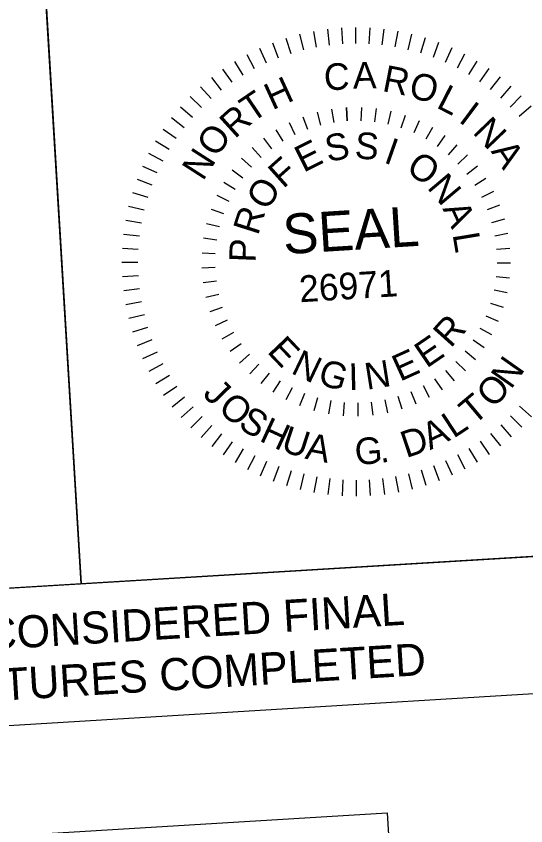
# Model space of a CAD drawing. Extents: x 2110128 to 2112690, y 669500 to 671339.
# Drawn here: x 2112336.1 to 2112423.5, y 670613.2 to 670751.9 of the extents above; entities that cross this region are included whole.
import ezdxf

# ---------------------------------------------------------------- set-up
doc = ezdxf.new("R2010")
doc.units = 0
for name, color, linetype in [('Default', 7, 'Continuous'), ('Exist Roads Curbs Text', 7, 'Continuous'), ('Exist Utilities Power Transformer Cogo Comment', 7, 'Continuous'), ('Exist Utilities TV Test Hole SUE LOS A Text', 7, 'Continuous'), ('Exist Utilities Water Fire Hydrant CELL', 7, 'Continuous')]:
    doc.layers.add(name, color=color, linetype=linetype)

msp = doc.modelspace()

# ---------------------------------------------------------------- linework, layer by layer
at = {"layer": 'Default'}
for p, q in [((2112384.7, 670748.79), (2112385.36, 670746.13)), ((2112387.07, 670749.3), (2112387.57, 670746.61)), ((2112389.47, 670749.67), (2112389.8, 670746.95)), ((2112391.88, 670749.89), (2112392.06, 670747.16)), ((2112394.31, 670749.97), (2112394.32, 670747.24)), ((2112396.73, 670749.9), (2112396.58, 670747.17)), ((2112399.15, 670749.69), (2112398.83, 670746.97)), ((2112401.54, 670749.33), (2112401.06, 670746.64)), ((2112403.92, 670748.83), (2112403.27, 670746.16)), ((2112380.08, 670747.34), (2112381.05, 670744.78)), ((2112382.37, 670748.13), (2112383.19, 670745.52)), ((2112406.26, 670748.18), (2112405.44, 670745.56)), ((2112408.55, 670747.39), (2112407.59, 670744.83)), ((2112377.84, 670746.4), (2112378.97, 670743.91)), ((2112410.79, 670746.47), (2112409.67, 670743.97)), ((2112375.66, 670745.33), (2112376.94, 670742.92)), ((2112412.98, 670745.41), (2112411.71, 670742.99)), ((2112373.55, 670744.14), (2112374.97, 670741.8)), ((2112415.09, 670744.22), (2112413.68, 670741.88)), ((2112371.51, 670742.82), (2112373.08, 670740.57)), ((2112417.13, 670742.91), (2112415.58, 670740.66)), ((2112369.57, 670741.38), (2112371.26, 670739.23)), ((2112419.09, 670741.48), (2112417.4, 670739.32)), ((2112367.71, 670739.82), (2112369.52, 670737.78)), ((2112420.95, 670739.93), (2112419.14, 670737.88)), ((2112365.94, 670738.16), (2112367.88, 670736.23)), ((2112422.72, 670738.27), (2112420.79, 670736.33)), ((2112364.29, 670736.39), (2112366.34, 670734.58)), ((2112395.3, 670736.27), (2112395.22, 670733.99)), ((2112424.39, 670736.51), (2112422.34, 670734.69)), ((2112387.7, 670735.43), (2112388.27, 670733.22)), ((2112390.2, 670735.95), (2112390.56, 670733.7)), ((2112392.74, 670736.23), (2112392.88, 670733.96)), ((2112392.88, 670733.96), (2112392.74, 670736.23)), ((2112397.84, 670736.06), (2112397.55, 670733.8)), ((2112400.36, 670735.6), (2112399.84, 670733.38)), ((2112402.82, 670734.91), (2112402.09, 670732.74)), ((2112362.74, 670734.52), (2112364.89, 670732.84)), ((2112382.9, 670733.66), (2112383.89, 670731.61)), ((2112385.26, 670734.66), (2112386.04, 670732.52)), ((2112405.2, 670733.98), (2112404.27, 670731.9)), ((2112361.3, 670732.56), (2112363.56, 670731.02)), ((2112380.65, 670732.44), (2112381.84, 670730.49)), ((2112407.48, 670732.82), (2112406.35, 670730.84)), ((2112378.53, 670731.01), (2112379.9, 670729.18)), ((2112409.64, 670731.45), (2112408.32, 670729.58)), ((2112359.99, 670730.53), (2112362.33, 670729.12)), ((2112376.56, 670729.38), (2112378.1, 670727.69)), ((2112411.65, 670729.88), (2112410.16, 670728.15)), ((2112358.8, 670728.41), (2112361.23, 670727.14)), ((2112413.51, 670728.12), (2112411.86, 670726.54)), ((2112374.76, 670727.57), (2112376.46, 670726.04)), ((2112357.74, 670726.23), (2112360.24, 670725.11)), ((2112373.14, 670725.59), (2112374.97, 670724.23)), ((2112415.19, 670726.19), (2112413.39, 670724.77)), ((2112356.83, 670723.98), (2112359.38, 670723.02)), ((2112416.66, 670724.1), (2112414.75, 670722.87)), ((2112371.72, 670723.47), (2112373.67, 670722.29)), ((2112356.03, 670721.69), (2112358.65, 670720.88)), ((2112370.51, 670721.22), (2112372.56, 670720.23)), ((2112417.94, 670721.88), (2112415.91, 670720.85)), ((2112355.39, 670719.36), (2112358.05, 670718.71)), ((2112369.52, 670718.86), (2112371.66, 670718.08)), ((2112418.99, 670719.55), (2112416.87, 670718.72)), ((2112354.88, 670716.98), (2112357.58, 670716.5)), ((2112419.82, 670717.14), (2112417.63, 670716.51)), ((2112368.76, 670716.41), (2112370.97, 670715.85)), ((2112354.52, 670714.58), (2112357.24, 670714.26)), ((2112420.41, 670714.65), (2112418.17, 670714.23)), ((2112368.25, 670713.91), (2112370.5, 670713.56)), ((2112354.31, 670712.17), (2112357.04, 670712.01)), ((2112367.97, 670711.37), (2112370.25, 670711.24)), ((2112420.75, 670712.11), (2112418.48, 670711.91)), ((2112354.24, 670709.75), (2112356.98, 670709.75)), ((2112367.95, 670708.81), (2112370.22, 670708.9)), ((2112420.85, 670709.56), (2112418.57, 670709.58)), ((2112354.32, 670707.32), (2112357.05, 670707.49)), ((2112418.44, 670707.33), (2112420.71, 670707.09)), ((2112368.17, 670706.27), (2112370.43, 670706.57)), ((2112354.55, 670704.9), (2112357.26, 670705.24)), ((2112420.31, 670704.48), (2112418.07, 670704.94)), ((2112354.92, 670702.51), (2112357.6, 670703.01)), ((2112368.64, 670703.75), (2112370.85, 670704.28)), ((2112369.34, 670701.29), (2112371.5, 670702.03)), ((2112419.67, 670702), (2112417.49, 670702.68)), ((2112355.43, 670700.14), (2112358.08, 670700.8)), ((2112418.79, 670699.6), (2112416.69, 670700.48)), ((2112370.28, 670698.92), (2112372.36, 670699.86)), ((2112356.08, 670697.81), (2112358.69, 670698.62)), ((2112371.45, 670696.64), (2112373.42, 670697.78)), ((2112417.69, 670697.3), (2112415.68, 670698.37)), ((2112356.88, 670695.51), (2112359.44, 670696.49)), ((2112416.38, 670695.1), (2112414.48, 670696.37)), ((2112372.82, 670694.49), (2112374.69, 670695.81)), ((2112357.81, 670693.28), (2112360.31, 670694.41)), ((2112374.41, 670692.48), (2112376.13, 670693.97)), ((2112414.85, 670693.05), (2112413.09, 670694.49)), ((2112358.88, 670691.1), (2112361.3, 670692.37)), ((2112376.18, 670690.63), (2112377.74, 670692.28)), ((2112413.14, 670691.15), (2112411.52, 670692.76)), ((2112378.11, 670688.96), (2112379.52, 670690.76)), ((2112411.25, 670689.43), (2112409.79, 670691.19)), ((2112360.07, 670688.99), (2112362.41, 670690.41)), ((2112380.2, 670687.49), (2112381.42, 670689.42)), ((2112409.2, 670687.9), (2112407.92, 670689.79)), ((2112361.39, 670686.95), (2112363.64, 670688.51)), ((2112382.42, 670686.23), (2112383.46, 670688.26)), ((2112407.01, 670686.57), (2112405.93, 670688.58)), ((2112362.84, 670685), (2112364.99, 670686.69)), ((2112384.76, 670685.18), (2112385.59, 670687.31)), ((2112387.18, 670684.37), (2112387.81, 670686.56)), ((2112402.31, 670684.58), (2112401.63, 670686.76)), ((2112404.71, 670685.46), (2112403.82, 670687.56)), ((2112364.39, 670683.14), (2112366.44, 670684.96)), ((2112390.06, 670686.04), (2112389.65, 670683.79)), ((2112392.21, 670683.46), (2112392.39, 670685.73)), ((2112394.76, 670683.37), (2112394.73, 670685.65)), ((2112397.31, 670683.53), (2112397.06, 670685.79)), ((2112399.84, 670683.93), (2112399.37, 670686.16)), ((2112424.49, 670683.26), (2112422.44, 670685.07)), ((2112366.06, 670681.38), (2112367.99, 670683.32)), ((2112422.83, 670681.5), (2112420.9, 670683.43)), ((2112367.83, 670679.72), (2112369.64, 670681.77)), ((2112421.07, 670679.83), (2112419.25, 670681.87)), ((2112369.69, 670678.17), (2112371.38, 670680.33)), ((2112419.21, 670678.27), (2112417.52, 670680.42)), ((2112371.65, 670676.74), (2112373.2, 670678.99)), ((2112417.26, 670676.83), (2112415.7, 670679.08)), ((2112373.69, 670675.43), (2112375.1, 670677.77)), ((2112375.8, 670674.24), (2112377.07, 670676.66)), ((2112413.12, 670674.32), (2112411.84, 670676.74)), ((2112415.23, 670675.51), (2112413.81, 670677.85)), ((2112377.99, 670673.18), (2112379.1, 670675.68)), ((2112410.94, 670673.25), (2112409.81, 670675.74)), ((2112380.23, 670672.26), (2112381.19, 670674.82)), ((2112382.52, 670671.47), (2112383.33, 670674.09)), ((2112406.41, 670671.52), (2112405.59, 670674.13)), ((2112408.7, 670672.31), (2112407.73, 670674.88)), ((2112384.86, 670670.82), (2112385.51, 670673.49)), ((2112387.23, 670670.32), (2112387.72, 670673.01)), ((2112389.63, 670669.96), (2112389.95, 670672.68)), ((2112392.05, 670669.75), (2112392.2, 670672.48)), ((2112396.89, 670669.76), (2112396.72, 670672.49)), ((2112399.31, 670669.98), (2112398.98, 670672.7)), ((2112401.71, 670670.35), (2112401.21, 670673.04)), ((2112404.07, 670670.86), (2112403.42, 670673.52)), ((2112394.47, 670669.68), (2112394.46, 670672.41))]:
    msp.add_line(p, q, dxfattribs=at)
at = {"layer": 'Exist Roads Curbs Text'}
msp.add_line((2112340.47, 670766.94), (2112347.27, 670654.69), dxfattribs=at)
for points in [[(2112340.47, 670766.94), (2112440.28, 670772.99), (2112447.09, 670660.69), (2112347.27, 670654.64)], [(2112240.6, 670760.89), (2112340.47, 670766.94), (2112347.27, 670654.64), (2112247.4, 670648.59)]]:
    msp.add_lwpolyline(points, close=True, dxfattribs=at)
at = {"layer": 'Exist Utilities Power Transformer Cogo Comment'}
for p, q in [((2112247.4, 670648.59), (2112447.08, 670660.69)), ((2112448.5, 670637.24), (2112248.83, 670625.13))]:
    msp.add_line(p, q, dxfattribs=at)
at = {"layer": 'Exist Utilities TV Test Hole SUE LOS A Text'}
msp.add_lwpolyline([(2111022.58, 670196.24), (2110993.69, 670672.84), (2112191.44, 670745.43), (2112200.05, 670603.34), (2112399.74, 670615.44), (2112420.01, 670280.93)], close=True, dxfattribs=at)
at = {"layer": 'Exist Utilities Water Fire Hydrant CELL'}
msp.add_lwpolyline([(2110944.98, 670715.17), (2112189.1, 670790.57), (2112200.05, 670603.34), (2112399.74, 670615.44), (2112418.35, 670308.36), (2112421.12, 670262.68), (2110980.52, 670175.37)], close=True, dxfattribs=at)

# ---------------------------------------------------------------- texts
at = {"layer": 'Default'}
for s, height, rotation, p in [('C', 4.56, 0.9334, (2112388.9, 670739.24)), ('A', 4.56, 0.9334, (2112393.87, 670739.46)), ('R', 4.56, 348.9241, (2112398.73, 670739.09)), ('O', 4.56, 345.8673, (2112403.22, 670738.06)), ('H', 4.56, 24.6441, (2112380.03, 670735.75)), ('T', 4.56, 34.0761, (2112376.49, 670733.54)), ('L', 4.56, 332.731, (2112407.98, 670736.32)), ('R', 4.56, 42.237, (2112373.59, 670730.8)), ('I', 4.56, 323.1556, (2112411.81, 670733.91)), ('N', 4.56, 313.8611, (2112414.22, 670731.91)), ('O', 4.56, 55.2938, (2112370.49, 670727.53)), ('E', 4.56, 26.5208, (2112385.38, 670725.06)), ('S', 4.56, 11.2246, (2112389.56, 670726.89)), ('S', 4.56, 355.9283, (2112394.07, 670727.55)), ('I', 4.56, 340.6321, (2112398.97, 670726.87)), ('A', 4.56, 304.0936, (2112417.43, 670728.74)), ('N', 4.56, 57.2532, (2112368.12, 670723.53)), ('F', 4.56, 41.8171, (2112381.9, 670722.25)), ('O', 4.56, 325.3358, (2112402.75, 670725.33)), ('O', 4.56, 57.1133, (2112379.11, 670718.4)), ('N', 4.56, 310.0396, (2112406.44, 670722.5)), ('R', 4.56, 72.4096, (2112377.56, 670714.2)), ('SEAL', 6.841, 3.5765, (2112382.03, 670711.11)), ('A', 4.56, 294.7434, (2112409.17, 670718.93)), ('L', 4.56, 279.4471, (2112410.93, 670714.52)), ('P', 4.56, 87.7058, (2112377.16, 670709.65)), ('26971', 4.557, 3.5765, (2112384.76, 670702.88)), ('R', 4.56, 48.1414, (2112410.61, 670694.93)), ('E', 4.56, 313.6466, (2112378.99, 670694.36)), ('E', 4.56, 34.3703, (2112406.48, 670691.49)), ('N', 4.56, 334.5016, (2112383.05, 670690.81)), ('E', 4.56, 24.3844, (2112401.93, 670689.25)), ('N', 4.56, 54.8741, (2112420.96, 670687.84)), ('G', 4.56, 343.2679, (2112387.63, 670688.95)), ('I', 4.56, 1.3627, (2112393.14, 670687.84)), ('N', 4.56, 8.9923, (2112396.24, 670687.88)), ('J', 4.56, 314.4356, (2112367.94, 670687.04)), ('O', 4.56, 47.4695, (2112417.95, 670684.56)), ('O', 4.56, 320.6458, (2112370.52, 670684.34)), ('T', 4.56, 40.065, (2112414.53, 670681.7)), ('S', 4.56, 328.0503, (2112373.97, 670681.51)), ('L', 4.56, 33.2577, (2112411.09, 670679.48)), ('H', 4.56, 335.216, (2112377.62, 670679.21)), ('A', 4.56, 25.8532, (2112407.08, 670677.54)), ('U', 4.56, 342.0233, (2112381.32, 670677.47)), ('D', 4.56, 18.6875, (2112402.99, 670676.17)), ('A', 4.56, 349.3084, (2112385.49, 670676.11)), ('G', 4.56, 4.1174, (2112394.32, 670675.01)), ('.', 4.56, 11.283, (2112398.62, 670675.31))]:
    msp.add_text(s, height=height, rotation=rotation, dxfattribs=at).set_placement(p)
at = {"layer": 'Exist Utilities Power Transformer Cogo Comment'}
for s, p in [('DOCUMENT NOT CONSIDERED FINAL', (2112269.06, 670639.54)), ('UNLESS ALL SIGNATURES COMPLETED', (2112264.53, 670630.45))]:
    msp.add_text(s, height=5.5, rotation=3.4682, dxfattribs=at).set_placement(p)

doc.saveas('drawing.dxf')
